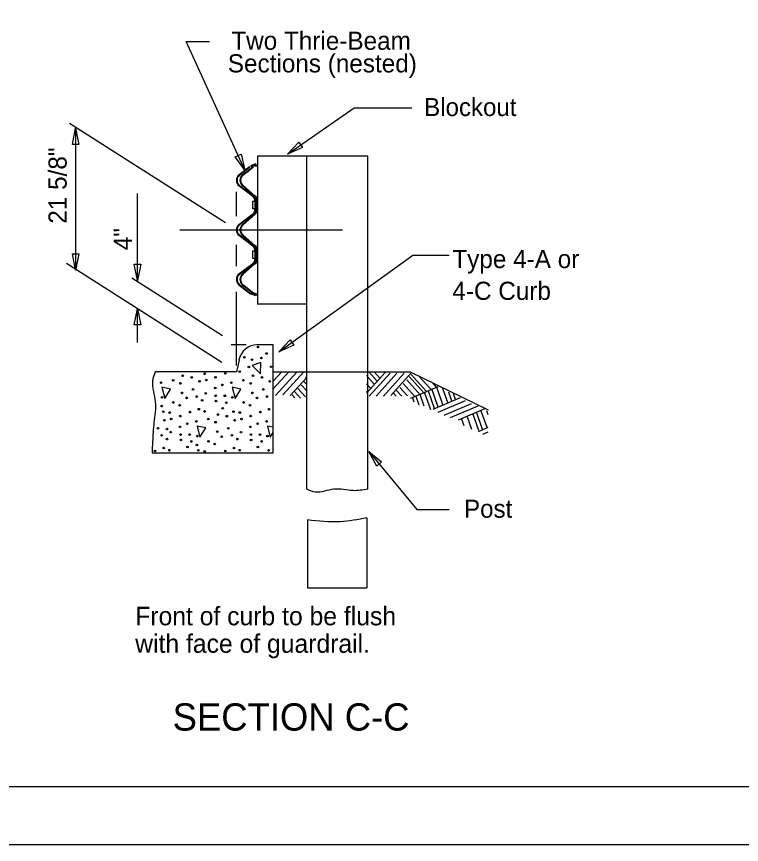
# Model space of a CAD drawing. Extents: x 0 to 34, y 0 to 22.
# Drawn here: x 18.56 to 24.84, y 0 to 7.17 of the extents above; entities that cross this region are included whole.
import ezdxf

# ---------------------------------------------------------------- set-up
doc = ezdxf.new("R2010")
doc.units = 0
for name, color, linetype in [('SH_Border', 7, 'Continuous'), ('SH_Cut_Line', 7, 'Continuous'), ('ST_Details', 7, 'Continuous'), ('ST_Text', 7, 'Continuous')]:
    doc.layers.add(name, color=color, linetype=linetype)

msp = doc.modelspace()

# ---------------------------------------------------------------- linework, layer by layer
at = {"layer": 'SH_Border'}
msp.add_lwpolyline([(2, 21.5), (33.5, 21.5), (33.5, 0.5), (2, 0.5)], close=True, dxfattribs=at)
at = {"layer": 'SH_Cut_Line'}
msp.add_lwpolyline([(0, 0), (34, 0), (34, 22), (0, 22)], close=True, dxfattribs=at)
at = {"layer": 'ST_Details'}
for p, q in [((20.6506, 5.9595), (21.0746, 5.9595)), ((20.6506, 4.6782), (20.6506, 5.9595)), ((21.0746, 5.9595), (21.6047, 5.9595)), ((21.0746, 3.0752), (21.0746, 5.9595)), ((21.6047, 3.0752), (21.6047, 5.9595)), ((20.6334, 5.891), (20.5877, 5.8727)), ((20.5894, 5.8669), (20.6352, 5.8845)), ((20.6511, 5.8787), (20.6199, 5.8729)), ((20.6352, 5.8845), (20.6334, 5.891)), ((20.4872, 5.7965), (20.5784, 5.8682)), ((20.5821, 5.8627), (20.4909, 5.791)), ((20.5187, 5.7965), (20.6101, 5.8682)), ((20.6131, 5.8627), (20.5224, 5.791)), ((20.5373, 5.8104), (20.5396, 5.8159)), ((20.5659, 5.8201), (20.5685, 5.8251)), ((20.6511, 5.8724), (20.6211, 5.8669)), ((20.6072, 5.6087), (20.4877, 5.6999)), ((20.4914, 5.7047), (20.6104, 5.6142)), ((20.6226, 5.6087), (20.5192, 5.6999)), ((20.5227, 5.705), (20.6259, 5.6139)), ((20.5301, 5.6755), (20.5262, 5.6702)), ((20.5592, 5.6727), (20.5562, 5.6674)), ((20.4649, 5.4379), (20.4649, 5.6492)), ((20.5681, 5.6465), (20.5644, 5.6412)), ((20.5956, 5.6405), (20.5926, 5.6352)), ((20.6274, 5.502), (20.6274, 5.5655)), ((20.6336, 5.5547), (20.6274, 5.5547)), ((20.6336, 5.5655), (20.6336, 5.502)), ((20.6431, 5.502), (20.6431, 5.5655)), ((20.6486, 5.5547), (20.6431, 5.5547)), ((20.6486, 5.5655), (20.6486, 5.502)), ((20.4877, 5.3675), (20.6072, 5.4587)), ((20.6104, 5.4534), (20.4914, 5.3629)), ((20.5192, 5.3675), (20.6226, 5.4587)), ((20.6259, 5.4535), (20.5227, 5.3627)), ((20.6336, 5.5127), (20.6274, 5.5127)), ((20.6486, 5.5127), (20.6431, 5.5127)), ((20.5301, 5.3919), (20.5262, 5.3972)), ((20.5592, 5.3949), (20.5562, 5.4002)), ((20.5681, 5.4209), (20.5644, 5.4262)), ((20.5956, 5.427), (20.5926, 5.4324)), ((19.9766, 5.3192), (21.3831, 5.3192)), ((20.6072, 5.1797), (20.4877, 5.2709)), ((20.4914, 5.2757), (20.6104, 5.1844)), ((20.6237, 5.1787), (20.5192, 5.2709)), ((20.5224, 5.2757), (20.6259, 5.1847)), ((20.5301, 5.2465), (20.5262, 5.2412)), ((20.5592, 5.2434), (20.5562, 5.2384)), ((20.4649, 5.0054), (20.4649, 5.1915)), ((20.5681, 5.2175), (20.5644, 5.2122)), ((20.5956, 5.2114), (20.5926, 5.2064)), ((20.6274, 5.073), (20.6274, 5.1364)), ((20.6336, 5.1255), (20.6274, 5.1255)), ((20.6336, 5.1364), (20.6336, 5.073)), ((20.6431, 5.073), (20.6431, 5.1364)), ((20.6486, 5.1255), (20.6431, 5.1255)), ((20.6486, 5.1364), (20.6486, 5.073)), ((20.4877, 4.9385), (20.6072, 5.0297)), ((20.6104, 5.0244), (20.4914, 4.9332)), ((20.5192, 4.9385), (20.6226, 5.0295)), ((20.6259, 5.0245), (20.5224, 4.9332)), ((20.6336, 5.0837), (20.6274, 5.0837)), ((20.6486, 5.0837), (20.6431, 5.0837)), ((20.5301, 4.9629), (20.5262, 4.9682)), ((20.5592, 4.9657), (20.5562, 4.9712)), ((20.5681, 4.992), (20.5644, 4.9974)), ((20.5956, 4.9979), (20.5926, 5.0032)), ((20.5784, 4.7702), (20.4872, 4.8419)), ((20.4909, 4.8474), (20.5821, 4.7757)), ((20.6101, 4.7702), (20.5187, 4.8419)), ((20.5224, 4.8474), (20.6131, 4.7757)), ((20.5301, 4.8162), (20.5269, 4.8109)), ((20.5616, 4.8162), (20.5579, 4.8109)), ((20.4649, 4.145), (20.4649, 4.7842)), ((20.5677, 4.787), (20.5642, 4.7815)), ((20.6334, 4.7474), (20.5877, 4.7659)), ((20.5894, 4.7717), (20.6352, 4.7539)), ((20.5989, 4.7865), (20.5959, 4.7817)), ((20.6511, 4.7595), (20.6199, 4.7655)), ((20.6211, 4.7717), (20.6511, 4.766)), ((20.6352, 4.7539), (20.6334, 4.7474)), ((20.6459, 4.68), (21.0701, 4.68)), ((20.6506, 4.6782), (21.0746, 4.6782)), ((20.5511, 4.3254), (20.4214, 4.3254)), ((20.7831, 4.3254), (20.6421, 4.3254)), ((20.7831, 3.3899), (20.7831, 4.3254)), ((20.4879, 4.1925), (20.4649, 4.0915)), ((20.6757, 4.1707), (20.6032, 4.1465)), ((20.6734, 4.0745), (20.6757, 4.1707)), ((19.7576, 4.0805), (19.7642, 4.0915)), ((20.4649, 4.0915), (19.7626, 4.0915)), ((20.6032, 4.1465), (20.6734, 4.0745)), ((20.7822, 3.9395), (20.9212, 4.093)), ((20.7831, 4.0915), (21.0746, 4.0915)), ((20.7849, 4.009), (20.8562, 4.0877)), ((20.8684, 3.891), (21.0484, 4.0897)), ((21.0746, 4.0915), (21.9707, 4.0915)), ((21.6824, 4.0119), (21.6112, 4.0904)), ((21.7082, 4.0362), (21.6597, 4.0897)), ((21.9707, 4.0915), (22.6464, 3.7605)), ((20.8046, 3.8852), (20.9847, 4.0839)), ((20.9321, 3.8852), (21.0746, 4.0424)), ((21.0746, 3.9799), (21.0434, 4.0142)), ((21.0746, 4.0325), (21.0647, 4.0434)), ((21.5932, 3.9062), (21.7544, 4.0839)), ((21.6596, 3.9845), (21.5932, 4.0577)), ((21.6169, 3.8794), (21.7969, 4.078)), ((21.6752, 3.8794), (21.8552, 4.078)), ((21.7389, 3.8794), (21.9191, 4.078)), ((21.8026, 3.8852), (21.9827, 4.0839)), ((22.0589, 3.8897), (21.9406, 4.0202)), ((22.0926, 3.9052), (21.9617, 4.0494)), ((22.1104, 3.9247), (21.9794, 4.0689)), ((22.0157, 4.066), (22.0096, 4.0727)), ((22.1494, 3.941), (22.0466, 4.0542)), ((19.8204, 3.9574), (19.8451, 3.86)), ((19.8952, 3.9422), (19.8204, 3.9574)), ((19.8451, 3.86), (19.8952, 3.9422)), ((20.4294, 3.9574), (20.4541, 3.86)), ((20.5042, 3.9422), (20.4294, 3.9574)), ((20.4541, 3.86), (20.5042, 3.9422)), ((21.0637, 3.8749), (20.9957, 3.9497)), ((21.0746, 3.9274), (21.0274, 3.979)), ((21.6289, 3.948), (21.5932, 3.9874)), ((21.9474, 3.8837), (21.8821, 3.9557)), ((22.0084, 3.8807), (21.9087, 3.9909)), ((21.9764, 3.863), (22.2142, 3.9639)), ((22.2129, 3.7847), (22.1577, 3.9429)), ((22.2001, 3.9582), (22.1671, 3.9944)), ((22.2541, 3.8054), (22.2006, 3.9582)), ((22.2987, 3.8154), (22.2534, 3.9454)), ((20.9709, 3.8662), (20.9479, 3.8912)), ((21.0212, 3.863), (20.9691, 3.9205)), ((21.5997, 3.9159), (21.5932, 3.923)), ((21.8492, 3.8807), (21.8219, 3.9109)), ((21.8971, 3.8807), (21.8504, 3.9324)), ((22.0496, 3.803), (22.0232, 3.8787)), ((22.0927, 3.7947), (22.0582, 3.8935)), ((22.1489, 3.7607), (22.0982, 3.9062)), ((22.1804, 3.7737), (22.1286, 3.923)), ((22.3311, 3.8382), (22.3046, 3.9139)), ((22.3627, 3.8515), (22.3456, 3.9002)), ((22.0049, 3.8282), (21.9931, 3.8615)), ((22.1704, 3.7679), (22.4081, 3.8689)), ((22.2119, 3.7412), (22.4497, 3.8422)), ((22.2652, 3.715), (22.5031, 3.816)), ((22.3207, 3.6942), (22.5586, 3.7952)), ((22.3882, 3.674), (22.6259, 3.775)), ((22.5651, 3.5825), (22.5134, 3.7305)), ((22.5979, 3.5922), (22.5472, 3.7374)), ((22.6364, 3.6087), (22.5871, 3.7499)), ((22.6464, 3.7184), (22.6346, 3.7522)), ((22.4387, 3.622), (22.4189, 3.6784)), ((22.5052, 3.5927), (22.4681, 3.6992)), ((20.1249, 3.6215), (20.1496, 3.5242)), ((20.1997, 3.6064), (20.1249, 3.6215)), ((20.1496, 3.5242), (20.1997, 3.6064)), ((20.7341, 3.6215), (20.7586, 3.5242)), ((20.7831, 3.6115), (20.7341, 3.6215)), ((22.5634, 3.5754), (22.6464, 3.6107)), ((22.6001, 3.5512), (22.6464, 3.5709)), ((19.7342, 3.3899), (20.7831, 3.3899)), ((21.0807, 2.8084), (21.0807, 2.2224)), ((21.5959, 2.8282), (21.5959, 2.2224)), ((21.0807, 2.2224), (21.5959, 2.2224))]:
    msp.add_line(p, q, dxfattribs=at)
for points in [[(20.6274, 5.564), (20.6041, 5.564), (20.6041, 5.504), (20.6274, 5.504)], [(20.6274, 5.1344), (20.6041, 5.1344), (20.6041, 5.0742), (20.6274, 5.0742)], [(20.7586, 3.5242), (20.7831, 3.5644)]]:
    msp.add_lwpolyline(points, dxfattribs=at)
for centre, major_axis, start_param, end_param in [((20.5185, 5.7483), (0, 0.059), 0.619407, 2.535258), ((20.5185, 5.7483), (0, 0.0528), 0.619456, 2.535258), ((20.5499, 5.7483), (0, -0.059), 3.760999, 5.67685), ((20.5499, 5.7483), (0, -0.0528), 3.761049, 5.67685), ((20.5798, 5.5654), (0, 0.0528), 4.712389, 5.676899), ((20.5798, 5.5654), (0, 0.059), 4.712389, 5.676899), ((20.5954, 5.5654), (0, 0.0528), 4.712389, 5.676899), ((20.5954, 5.5654), (0, 0.059), 4.712389, 5.676899), ((20.5798, 5.5021), (0, 0.0528), 3.747879, 4.712389), ((20.5798, 5.5021), (0, 0.059), 3.747879, 4.712389), ((20.5954, 5.5021), (0, -0.0528), 0.606287, 1.570796), ((20.5954, 5.5021), (0, -0.059), 0.606287, 1.570796), ((20.5185, 5.3192), (0, 0.059), 0.606335, 2.535258), ((20.5185, 5.3192), (0, 0.0528), 0.606287, 2.535306), ((20.5499, 5.3192), (0, 0.059), 0.606335, 2.535258), ((20.5499, 5.3192), (0, 0.0528), 0.606287, 2.535306), ((20.5798, 5.1363), (0, 0.0528), 4.712389, 5.676899), ((20.5798, 5.1363), (0, 0.059), 4.712389, 5.676899), ((20.5954, 5.1363), (0, 0.0528), 4.712389, 5.676899), ((20.5954, 5.1363), (0, 0.059), 4.712389, 5.676899), ((20.5798, 5.073), (0, 0.0528), 3.747879, 4.712389), ((20.5798, 5.073), (0, 0.059), 3.747879, 4.712389), ((20.5954, 5.073), (0, -0.0528), 0.606287, 1.570796), ((20.5954, 5.073), (0, -0.059), 0.606287, 1.570796), ((20.5185, 4.8901), (0, 0.059), 0.606335, 2.522186), ((20.5185, 4.8901), (0, 0.0528), 0.606335, 2.522137), ((20.5499, 4.8901), (0, 0.059), 0.606335, 2.522186), ((20.5499, 4.8901), (0, 0.0528), 0.606335, 2.522137), ((20.6058, 4.8253), (0, -0.0627), 5.781617, 5.962258), ((20.6042, 4.8142), (0, -0.0456), 5.719613, 5.91876), ((20.6219, 4.8142), (0, -0.0456), 5.719613, 5.91876), ((20.6244, 4.7927), (0, -0.0274), 5.663747, 6.108625), ((20.6244, 4.7927), (0, -0.0211), 5.663747, 6.108625), ((20.6421, 4.1499), (0, 0.1754), 0, 1.325818)]:
    msp.add_ellipse(centre, major_axis=major_axis, ratio=0.906762, start_param=start_param, end_param=end_param, dxfattribs=at)
for centre, major_axis in [((20.6528, 4.3057), (-0.00718, 0)), ((20.7254, 4.2498), (-0.00718, 0)), ((20.534, 4.2161), (-0.00718, 0)), ((20.6003, 4.1955), (-0.00718, 0)), ((20.6819, 4.2103), (-0.00718, 0)), ((20.3687, 4.0776), (0, 0.00718)), ((20.4937, 4.0924), (0, 0.00718)), ((20.5731, 4.133), (-0.00718, 0)), ((20.7653, 4.1347), (-0.00718, 0)), ((19.9175, 4.0178), (0, 0.00718)), ((20.0006, 4.0568), (0, 0.00718)), ((20.0781, 4.0425), (0, 0.00718)), ((20.1455, 4.0081), (0, 0.00718)), ((20.1908, 4.0742), (0, 0.00718)), ((20.2047, 4.019), (0, 0.00718)), ((20.2845, 4.0434), (0, 0.00718)), ((20.5265, 4.0178), (0, 0.00718)), ((20.6096, 4.0568), (0, 0.00718)), ((20.6871, 4.0425), (0, 0.00718)), ((20.7545, 4.0081), (0, 0.00718)), ((19.8131, 3.9969), (0, 0.00718)), ((19.98, 3.9906), (0, 0.00718)), ((20.0902, 3.938), (0, 0.00718)), ((20.2815, 3.9506), (0, 0.00718)), ((20.344, 3.9778), (0, 0.00718)), ((20.4221, 3.9969), (0, 0.00718)), ((20.589, 3.9906), (0, 0.00718)), ((20.6992, 3.938), (0, 0.00718)), ((19.8213, 3.8699), (0, 0.00718)), ((19.9948, 3.9089), (0, 0.00718)), ((20.0343, 3.8654), (0, 0.00718)), ((20.1223, 3.8772), (0, 0.00718)), ((20.2001, 3.9044), (0, 0.00718)), ((20.2865, 3.8835), (0, 0.00718)), ((20.3654, 3.8835), (0, 0.00718)), ((20.4303, 3.8699), (0, 0.00718)), ((20.6039, 3.9089), (0, 0.00718)), ((20.6433, 3.8654), (0, 0.00718)), ((20.7313, 3.8772), (0, 0.00718)), ((19.818, 3.7938), (0, 0.00718)), ((19.9192, 3.8255), (0, 0.00718)), ((19.9734, 3.8019), (0, 0.00718)), ((20.1686, 3.8442), (0, 0.00718)), ((20.2889, 3.8373), (0, 0.00718)), ((20.3786, 3.8237), (0, 0.00718)), ((20.5282, 3.8255), (0, 0.00718)), ((20.5824, 3.8019), (0, 0.00718)), ((19.8312, 3.7466), (0, 0.00718)), ((19.8863, 3.7384), (0, 0.00718)), ((20.0642, 3.7418), (0, 0.00718)), ((20.1398, 3.7672), (0, 0.00718)), ((20.19, 3.7481), (0, 0.00718)), ((20.3051, 3.7209), (0, 0.00718)), ((20.3464, 3.7756), (0, 0.00718)), ((20.4402, 3.7466), (0, 0.00718)), ((20.4953, 3.7384), (0, 0.00718)), ((20.6732, 3.7418), (0, 0.00718)), ((20.7489, 3.7672), (0, 0.00718)), ((19.841, 3.6722), (0, 0.00718)), ((19.9002, 3.6832), (0, 0.00718)), ((19.98, 3.7076), (0, 0.00718)), ((20.1176, 3.6611), (0, 0.00718)), ((20.222, 3.6819), (0, 0.00718)), ((20.2845, 3.6547), (0, 0.00718)), ((20.3826, 3.7067), (0, 0.00718)), ((20.45, 3.6722), (0, 0.00718)), ((20.5093, 3.6832), (0, 0.00718)), ((20.589, 3.7076), (0, 0.00718)), ((20.7266, 3.6611), (0, 0.00718)), ((19.7857, 3.6022), (0, 0.00718)), ((19.8633, 3.5952), (0, 0.00718)), ((19.977, 3.6148), (0, 0.00718)), ((20.0394, 3.642), (0, 0.00718)), ((20.3947, 3.6022), (0, 0.00718)), ((20.586, 3.6148), (0, 0.00718)), ((20.6485, 3.642), (0, 0.00718)), ((19.8178, 3.5414), (0, 0.00718)), ((19.8641, 3.5084), (0, 0.00718)), ((19.8956, 3.5686), (0, 0.00718)), ((19.9819, 3.5477), (0, 0.00718)), ((20.0609, 3.5477), (0, 0.00718)), ((20.1258, 3.5341), (0, 0.00718)), ((20.2993, 3.5731), (0, 0.00718)), ((20.3388, 3.5296), (0, 0.00718)), ((20.4268, 3.5414), (0, 0.00718)), ((20.4731, 3.5084), (0, 0.00718)), ((20.5046, 3.5686), (0, 0.00718)), ((20.591, 3.5477), (0, 0.00718)), ((20.6699, 3.5477), (0, 0.00718)), ((20.7348, 3.5341), (0, 0.00718)), ((19.9844, 3.5015), (0, 0.00718)), ((20.0419, 3.4398), (0, 0.00718)), ((20.0741, 3.4879), (0, 0.00718)), ((20.1225, 3.4579), (0, 0.00718)), ((20.2237, 3.4897), (0, 0.00718)), ((20.2779, 3.4661), (0, 0.00718)), ((20.5934, 3.5015), (0, 0.00718)), ((20.651, 3.4398), (0, 0.00718)), ((20.6831, 3.4879), (0, 0.00718)), ((19.7596, 3.406), (0, 0.00718)), ((19.8353, 3.4313), (0, 0.00718)), ((19.8855, 3.4123), (0, 0.00718)), ((20.1357, 3.4108), (0, 0.00718)), ((20.1908, 3.4026), (0, 0.00718)), ((20.3687, 3.406), (0, 0.00718)), ((20.4443, 3.4313), (0, 0.00718)), ((20.4945, 3.4123), (0, 0.00718)), ((20.7447, 3.4108), (0, 0.00718))]:
    msp.add_ellipse(centre, major_axis=major_axis, ratio=0.906762, dxfattribs=at)
for points in [[(19.7626, 4.0915), (19.7392, 4.0107), (19.7626, 3.8314), (19.7509, 3.6519), (19.7392, 3.4854), (19.7342, 3.3899)], [(21.6047, 3.0752), (21.4731, 3.0624), (21.3106, 3.0752), (21.1479, 3.0495), (21.0746, 3.0752)], [(21.5959, 2.8282), (21.3629, 2.7924), (21.0807, 2.8085)]]:
    msp.add_spline(points, degree=3, dxfattribs=at)
at = {"layer": 'ST_Text'}
for p, q in [((20.3706, 5.3794), (19.0182, 6.2402)), ((19.0724, 6.2057), (19.0724, 4.9714)), ((19.6082, 4.8817), (19.6082, 5.6332)), ((20.3402, 4.1709), (18.9949, 5.0274)), ((20.3442, 4.4022), (19.5586, 4.9025)), ((19.6082, 4.3455), (19.6082, 4.6367))]:
    msp.add_line(p, q, dxfattribs=at)
for points in [[(20.5391, 5.8374), (20.0297, 6.9497), (20.2336, 6.9497)], [(20.9073, 5.9763), (21.4852, 6.3758), (21.9864, 6.3758)], [(20.8332, 4.2634), (21.9932, 5.1002), (22.3096, 5.1012)], [(21.6126, 3.4006), (22.0289, 2.899), (22.3093, 2.899)]]:
    msp.add_lwpolyline(points, dxfattribs=at)
for points in [[(19.1004, 6.0592), (19.0444, 6.0592), (19.0724, 6.1992)], [(21.0066, 6.0789), (21.0384, 6.0329), (20.9073, 5.9763)], [(20.4553, 5.953), (20.5062, 5.9763), (20.5391, 5.8374)], [(19.0444, 5.1114), (19.1004, 5.1114), (19.0724, 4.9714)], [(19.5802, 5.0217), (19.6362, 5.0217), (19.6082, 4.8817)], [(19.6362, 4.4967), (19.5802, 4.4967), (19.6082, 4.6367)], [(20.9304, 4.368), (20.9632, 4.3226), (20.8332, 4.2634)], [(21.7235, 3.3108), (21.6805, 3.275), (21.6126, 3.4006)]]:
    msp.add_lwpolyline(points, close=True, dxfattribs=at)

# ---------------------------------------------------------------- texts
for s, height, p in [('Two Thrie-Beam', 0.1574, (20.4212, 6.8785)), ('Sections (nested)', 0.1574, (20.3908, 6.6824)), ('Blockout', 0.156, (22.0918, 6.3049)), ('Type 4-A or', 0.1574, (22.3362, 4.989)), ('4-C Curb', 0.1574, (22.3362, 4.7135)), ('Post', 0.156, (22.4375, 2.828)), ('Front of curb to be flush', 0.16, (19.5888, 1.8969)), ('with face of guardrail.', 0.16, (19.5888, 1.6589)), ('SECTION C-C', 0.2361, (19.9128, 0.9853))]:
    msp.add_text(s, height=height, dxfattribs=at).set_placement(p)
for s, p in [('21 5/8"', (18.9949, 5.3729)), ('4"', (19.5596, 5.1434))]:
    msp.add_text(s, height=0.1574, rotation=90, dxfattribs=at).set_placement(p)

doc.saveas('drawing.dxf')
